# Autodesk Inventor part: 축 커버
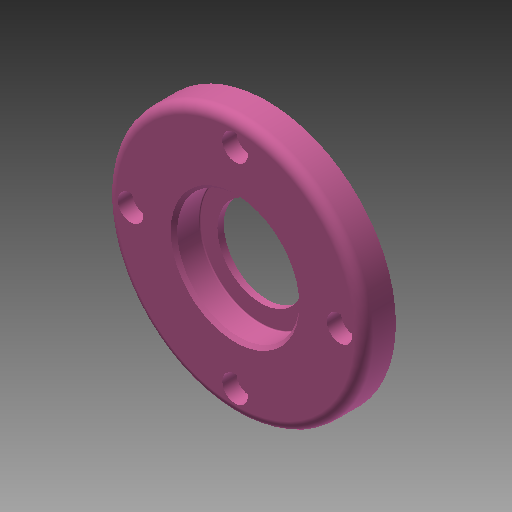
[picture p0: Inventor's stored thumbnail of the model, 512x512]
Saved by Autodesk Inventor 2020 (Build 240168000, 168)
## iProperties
Created: 2015-10
Part Number: 축 커버
Document SubType Name: Modeling
Designer: mdu
Density: 1 g/cm^3
Material: 강철, 연강
Appearance: 분홍색
Author: mdu
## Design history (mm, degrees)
sketch "스케치1"
  geometry: C1 r 40 at (0, 0) reference; C2 r 26 at (0, 0) reference; 1 further point
  node "참조1"
  node "참조2"
extrude "돌출1" new body sketch "스케치1" distance "d0" = 10; taper "d1" = 0 deg
extrude "돌출2" join sketch "스케치1" distance "d2" = 3; taper "d3" = 0 deg
hole "구멍1" diameter "d6" = 27; stored, may be unused: countersink angle "d10" = 90 deg, drill point angle "d12" = 118 deg; dims "d4" = 10, "d5" = 10, "d7" = 6, "d8" = 38, "d9" = 8, "d11" = 8
sketch "스케치2"
  geometry: C1 r 20 at (0, 0); 1 further point
  constraints: 1 centre point, 1 coincident
  dimensions: "d13" = 40 diameter of C1
extrude "돌출3" cut sketch "스케치2" distance "d14" = 3; taper "d15" = 0 deg
sketch "스케치3"
  geometry: C1 r 1.621 at (0, 32.5) reference; 1 further point
hole "구멍2" sketch "스케치3" at (0, 32.5) diameter "d16" = 4.5; stored, may be unused: countersink angle "d20" = 90 deg, drill point angle "d22" = 118 deg; dims "d17" = 6, "d18" = 8, "d19" = 4.4, "d21" = 8
fillet "모깎기1" dims "d26" = 3, "d27" = 0.3
chamfer "모따기1" distance "d28" = 1; stored, may be unused: second distance "d29" = 2, angle "d30" = 45 deg
node "솔리드1"
pattern_circular "원형 패턴1" dims angle "d24" = 360 deg
node "참조3"
